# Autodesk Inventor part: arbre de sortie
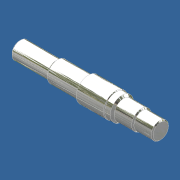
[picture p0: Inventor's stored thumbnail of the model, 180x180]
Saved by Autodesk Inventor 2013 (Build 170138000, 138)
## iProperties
Created: 2011-07
Part Number: arbre de sortie
Document SubType Name: Modeling
Designer: Laur
Density: 7.85 g/cm^3
Material: Acier allié
Mass: 2.98245 g
Surface Area: 3.97681 cm^2
Volume: 0.37993 cm^3
Author: Laur
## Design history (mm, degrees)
sketch "Esquisse1"
  geometry: L1 (0, 0)-(29, 0); L2 (0, 0)-(0, 1.57); L3 (0, 1.57)-(0.2, 1.77); L4 (0.2, 1.77)-(4.5, 1.77); L5 (4.5, 1.77)-(4.5, 1.77); L6 (4.5, 1.77)-(7, 1.77); L7 (7, 1.77)-(7, 1.77); L8 (7, 1.77)-(7.5, 1.77); L9 (11.53, 2.1)-(14.03, 2.1); L10 (14.03, 2.1)-(14.03, 2.5); L11 (14.03, 2.5)-(19.63, 2.5); L12 (19.63, 2.5)-(19.75, 2.38); L13 (19.75, 2.38)-(20.73, 2.38); L14 (20.73, 2.38)-(21.01, 2.1); L15 (21.01, 2.1)-(22.98, 2.1); L16 (22.98, 2.1)-(23.08, 2); L17 (23.08, 2)-(24.48, 2); L18 (24.48, 2)-(24.71, 1.77); L19 (24.71, 1.77)-(28.8, 1.77); L20 (28.8, 1.77)-(29, 1.57); L21 (29, 1.57)-(29, 0); L22 (7.73, 2)-(7.5, 1.77); L23 (7.73, 2)-(11.43, 2); L24 (11.43, 2)-(11.53, 2.1)
  constraints: 49 end point, 11 parallel, 7 perpendicular, 2 collinear, 1 horizontal
  dimensions: "d0" = 45 deg angle of L2 L3; "d1" = 45 deg angle of L15 L14 (= d0); "d2" = 45 deg angle of L17 L16 (= d0); "d3" = 0.2 distance from line of L2 L3.end; "d4" = 3.54 diameter of L4 L1; "d5" = 7 distance between parallel lines of L7 L2; "d6" = 3.54 diameter of L6 L1 (= d4); "d7" = 4.5 distance from line of L4.end L2; "d8" = 2.5 distance of L7.end L5.end; "d10" = 4.2 diameter of L9 L1; "d13" = 5.6 distance from line of L11.end L10; "d14" = 5 diameter of L11 L1; "d15" = 4.76 diameter of L13 L1; "d16" = 4.2 diameter of L15 L1; "d17" = 4 diameter of L17 L1; "d18" = 3.54 diameter of L19 L1 (= d4); "d19" = 1.1 horizontal distance of L13.end L11.end; "d21" = 2.25 horizontal distance of L15.end L13.end; "d22" = 1.5 horizontal distance of L17.end L15.end; "d23" = 0.2 horizontal distance of L20.end L19.end; "d24" = 29 distance between parallel lines of L21 L2; "d26" = 0.5 distance of L6.end L8.end; "d27" = 6.3 distance from line of L22.start L10; "d29" = 4 diameter of L23 L1; "d30" = 3.8 horizontal distance of L22.start L9.start
revolve "toutes les formes de l'arbre" sketch "Esquisse1" stored, may be unused: angle "d28" = 90 deg
node "Solide1"
node "Corps solides"
node "Corps surfaciques"
